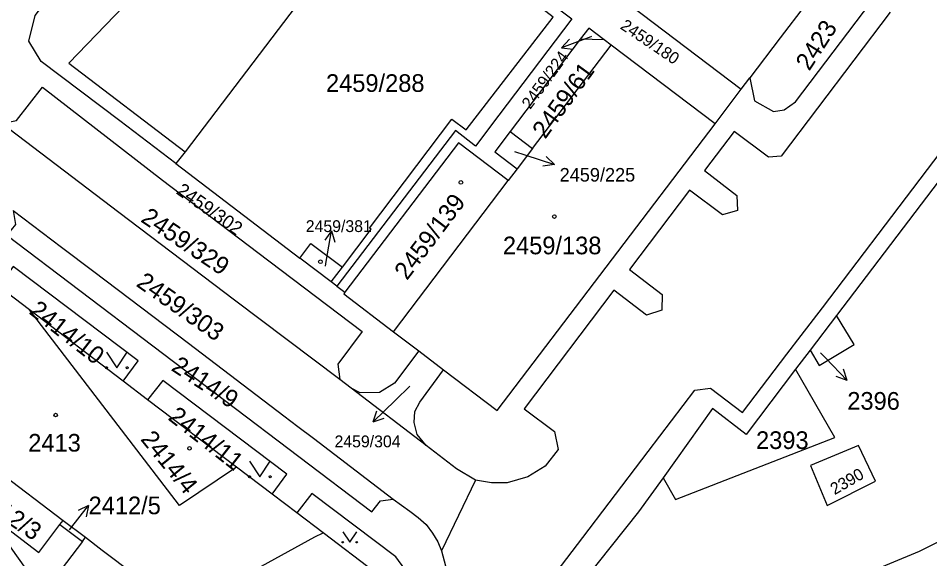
# Model space of a CAD drawing. Extents: x -606208 to -605570, y -1157873 to -1157573.
# Drawn here: x -605756.7 to -605669, y -1157686.5 to -1157634.5 of the extents above; entities that cross this region are included whole.
import ezdxf

# ---------------------------------------------------------------- set-up
doc = ezdxf.new("R2010")
doc.units = 0
doc.layers.add('Vrstva 62', color=7, linetype='Continuous')

msp = doc.modelspace()

# ---------------------------------------------------------------- linework, layer by layer
at = {"layer": 'Vrstva 62'}
for p, q in [((-605721.38, -1157621.96), (-605740.69, -1157647.37)), ((-605653.95, -1157631.43), (-605678, -1157663.1)), ((-605699.35, -1157632.1), (-605687.18, -1157641.34)), ((-605701.59, -1157636.26), (-605701.66, -1157636.28)), ((-605702.67, -1157636.52), (-605709.41, -1157645.4)), ((-605707.26, -1157647.03), (-605699.69, -1157637.08)), ((-605701.66, -1157636.28), (-605704.462, -1157637.355)), ((-605704.462, -1157637.355), (-605703.706, -1157636.529)), ((-605700.36, -1157636.57), (-605702.67, -1157636.52)), ((-605699.69, -1157637.08), (-605700.36, -1157636.57)), ((-605689.7, -1157644.66), (-605699.69, -1157637.08)), ((-605704.462, -1157637.355), (-605703.347, -1157637.464)), ((-605687.18, -1157641.34), (-605686.35, -1157640.24)), ((-605689.7, -1157644.66), (-605687.18, -1157641.34)), ((-605709.41, -1157645.4), (-605707.26, -1157647.03)), ((-605740.69, -1157647.37), (-605741.59, -1157648.49)), ((-605709, -1157647.32), (-605708.01, -1157647.65)), ((-605707.26, -1157647.03), (-605708.74, -1157648.98)), ((-605708.01, -1157647.65), (-605705.156, -1157648.577)), ((-605741.59, -1157648.49), (-605729.65, -1157657.58)), ((-605705.156, -1157648.577), (-605705.954, -1157647.792)), ((-605708.74, -1157648.98), (-605709.61, -1157650.13)), ((-605705.156, -1157648.577), (-605706.263, -1157648.744)), ((-605720.65, -1157664.67), (-605709.61, -1157650.13)), ((-605726.589, -1157654.975), (-605727.256, -1157655.874)), ((-605727.11, -1157657.93), (-605726.589, -1157654.975)), ((-605726.589, -1157654.975), (-605726.27, -1157656.048)), ((-605726.62, -1157659.88), (-605729.65, -1157657.58)), ((-605727.19, -1157658.35), (-605727.11, -1157657.93)), ((-605726.62, -1157659.88), (-605725.55, -1157658.46)), ((-605726.1, -1157660.28), (-605726.62, -1157659.88)), ((-605726.1, -1157660.28), (-605725.31, -1157660.88)), ((-605746.64, -1157669.44), (-605755.68, -1157662.57)), ((-605678, -1157663.1), (-605680.55, -1157666.45)), ((-605720.65, -1157664.67), (-605718.21, -1157666.52)), ((-605718.21, -1157666.52), (-605715.82, -1157668.34)), ((-605680.55, -1157666.45), (-605681.95, -1157668.29)), ((-605679.55, -1157666.71), (-605679.07, -1157667.2)), ((-605679.07, -1157667.2), (-605676.985, -1157669.359)), ((-605676.985, -1157669.359), (-605677.321, -1157668.29)), ((-605744.3, -1157671.22), (-605746.64, -1157669.44)), ((-605724.7, -1157670.12), (-605725.81, -1157669.27)), ((-605676.985, -1157669.359), (-605678.041, -1157668.986)), ((-605717.49, -1157675.62), (-605724.7, -1157670.12)), ((-605719.07, -1157669.91), (-605720.45, -1157671.26)), ((-605735.73, -1157677.72), (-605744.3, -1157671.22)), ((-605720.45, -1157671.26), (-605722.609, -1157673.345)), ((-605722.609, -1157673.345), (-605722.236, -1157672.289)), ((-605722.609, -1157673.345), (-605721.54, -1157673.009)), ((-605759.91, -1157677.16), (-605752.43, -1157682.83)), ((-605732.3, -1157680.32), (-605735.73, -1157677.72)), ((-605712.76, -1157678.96), (-605716.01, -1157685.76)), ((-605729.94, -1157682.1), (-605732.3, -1157680.32)), ((-605751.83, -1157683.75), (-605749.982, -1157681.385)), ((-605749.982, -1157681.385), (-605750.994, -1157681.866)), ((-605749.982, -1157681.385), (-605750.204, -1157682.483)), ((-605727.42, -1157684.02), (-605729.94, -1157682.1)), ((-605752.73, -1157683.23), (-605752.43, -1157682.83)), ((-605752.73, -1157683.23), (-605750.58, -1157684.86)), ((-605752.43, -1157682.83), (-605750.28, -1157684.46)), ((-605750.58, -1157684.86), (-605750.28, -1157684.46))]:
    msp.add_line(p, q, dxfattribs=at)
for points in [[(-605741.59, -1157648.49), (-605746.97, -1157644.39), (-605754.54, -1157638.66), (-605755.72, -1157636.71), (-605755.12, -1157634.23), (-605751.99, -1157630.1), (-605741.63, -1157616.42), (-605737.51, -1157610.98), (-605736.94, -1157610.24), (-605736.51, -1157609.73), (-605736.19, -1157609.53)], [(-605736.19, -1157609.53), (-605735.96, -1157609.49), (-605735.7, -1157609.4), (-605735.32, -1157609.39), (-605734.43, -1157609.77), (-605725.74, -1157616.38), (-605725.63, -1157617.79), (-605714.66, -1157626.08), (-605703.47, -1157634.55), (-605710.49, -1157643.82), (-605712.75, -1157646.8), (-605714.68, -1157645.32), (-605726.1, -1157660.28)], [(-605721.38, -1157621.96), (-605721.13, -1157621.62), (-605733.49, -1157612.23), (-605736.44, -1157620.16), (-605738.62, -1157619.25), (-605739.52, -1157620.49), (-605739.7, -1157620.36), (-605747.44, -1157630.54), (-605747.38, -1157630.72), (-605748.16, -1157631.81), (-605746.6, -1157633.34), (-605751.88, -1157638.81), (-605740.69, -1157647.37)], [(-605725.55, -1157658.46), (-605722.79, -1157654.79), (-605722.95, -1157654.71), (-605715.01, -1157644.22), (-605713.64, -1157645.23), (-605705.28, -1157634.41), (-605719.8, -1157623.18), (-605721.38, -1157621.96)], [(-605686.35, -1157640.24), (-605685.9, -1157642.45), (-605684.07, -1157643.47), (-605683.04, -1157643.33), (-605681.96, -1157642.56), (-605674.71, -1157633), (-605674.42, -1157631.08), (-605674.91, -1157629.9), (-605675.91, -1157628.98), (-605676.72, -1157628.38), (-605684.69, -1157622.37), (-605686.17, -1157624.31)], [(-605686.17, -1157624.31), (-605678.61, -1157630.05), (-605683.42, -1157636.39), (-605686.35, -1157640.24)], [(-605714.75, -1157700.25), (-605710.96, -1157695.68), (-605710.18, -1157694.65), (-605706.94, -1157690.4), (-605702.43, -1157684.48), (-605699.9, -1157681.15), (-605696.13, -1157676.2), (-605691.65, -1157670.31), (-605690.12, -1157670.1), (-605687.04, -1157672.45), (-605682.78, -1157666.84), (-605681.4, -1157665.03), (-605679.37, -1157662.36), (-605660.55, -1157637.61), (-605653.28, -1157627.99)], [(-605672.83, -1157633.91), (-605683.34, -1157647.76), (-605684.55, -1157647.87), (-605687.84, -1157645.41), (-605690.7, -1157649.16), (-605687.61, -1157651.55), (-605687.52, -1157653.02), (-605688.97, -1157653.43), (-605692.14, -1157651.06), (-605697.93, -1157658.7), (-605694.8, -1157661.08), (-605694.82, -1157662.59), (-605696.28, -1157663.07), (-605699.44, -1157660.68), (-605708.05, -1157672.09), (-605705.13, -1157674.27), (-605704.79, -1157676.02), (-605706.04, -1157677.6), (-605707.7, -1157678.63), (-605709.71, -1157679.22), (-605711.22, -1157679.22), (-605712.76, -1157678.96)], [(-605700.36, -1157636.57), (-605701.85, -1157635.44), (-605702.67, -1157636.52)], [(-605758.34, -1157644.62), (-605756.9, -1157644.34), (-605754.41, -1157641.15), (-605742.86, -1157650.08), (-605733.69, -1157657.06), (-605723.64, -1157664.65), (-605726.01, -1157667.78), (-605725.81, -1157669.27)], [(-605725.81, -1157669.27), (-605735.95, -1157661.62), (-605747.07, -1157653.21), (-605758.34, -1157644.62)], [(-605715.82, -1157668.34), (-605710.66, -1157672.26), (-605689.7, -1157644.66)], [(-605709.41, -1157645.4), (-605710.89, -1157647.35), (-605708.74, -1157648.98)], [(-605709.61, -1157650.13), (-605714.39, -1157646.5), (-605725.31, -1157660.88)], [(-605757.23, -1157653.01), (-605757.01, -1157654.35), (-605757.84, -1157655.37), (-605722.72, -1157682), (-605721.89, -1157680.95), (-605720.66, -1157680.78)], [(-605757.23, -1157653.01), (-605752.59, -1157656.53), (-605749.48, -1157658.89), (-605740.38, -1157665.78), (-605731.2, -1157672.77), (-605729.85, -1157673.79), (-605728.35, -1157674.93), (-605720.66, -1157680.78)], [(-605729.65, -1157657.58), (-605728.59, -1157656.17), (-605725.55, -1157658.46)], [(-605746.64, -1157669.44), (-605745.21, -1157667.49), (-605757.24, -1157658.39), (-605758.65, -1157660.32)], [(-605755.68, -1157662.57), (-605758.51, -1157660.43), (-605758.65, -1157660.32)], [(-605725.31, -1157660.88), (-605725.43, -1157661.04), (-605720.65, -1157664.67)], [(-605735.73, -1157677.72), (-605741.23, -1157681.4), (-605755.68, -1157662.57)], [(-605680.55, -1157666.45), (-605679.67, -1157667.91), (-605676.32, -1157665.89), (-605678, -1157663.1)], [(-605748.26, -1157666.639), (-605747.26, -1157668.14), (-605746.26, -1157666.639)], [(-605718.21, -1157666.52), (-605720.55, -1157669.64), (-605722, -1157670.51), (-605723.86, -1157670.55), (-605724.7, -1157670.12)], [(-605717.49, -1157675.62), (-605718.35, -1157674.56), (-605718.64, -1157673.42), (-605718.57, -1157672.35), (-605718.11, -1157671.46), (-605715.82, -1157668.34)], [(-605694.7, -1157678.73), (-605693.51, -1157680.83), (-605678.18, -1157674.85), (-605681.95, -1157668.29)], [(-605681.95, -1157668.29), (-605686.7, -1157674.55), (-605689.94, -1157672.07), (-605694.7, -1157678.73)], [(-605732.3, -1157680.32), (-605730.89, -1157678.38), (-605742.82, -1157669.36), (-605744.3, -1157671.22)], [(-605712.76, -1157678.96), (-605714.58, -1157677.86), (-605717.49, -1157675.62)], [(-605675.9, -1157675.63), (-605680.51, -1157677.56), (-605678.91, -1157681.4), (-605674.25, -1157679.05), (-605675.9, -1157675.63)], [(-605734.5, -1157677.129), (-605733.5, -1157678.63), (-605732.5, -1157677.129)], [(-605694.7, -1157678.73), (-605697.05, -1157682.01), (-605704.94, -1157691.92), (-605703.43, -1157692.73), (-605701.49, -1157693.29), (-605699.59, -1157693.2), (-605698.54, -1157697.8)], [(-605730.11, -1157697.93), (-605728.55, -1157699.16), (-605727.68, -1157699.35), (-605726.72, -1157699.08), (-605722.65, -1157695.57), (-605720.78, -1157693.46), (-605719.38, -1157691.41), (-605719.05, -1157689.39), (-605719.55, -1157687.53), (-605720.4, -1157686.35), (-605728.5, -1157680.23), (-605729.94, -1157682.1)], [(-605720.66, -1157680.78), (-605719.07, -1157681.94), (-605718.26, -1157682.55), (-605717.51, -1157683.23), (-605716.9, -1157684.05), (-605716.38, -1157684.91), (-605716.01, -1157685.76)], [(-605760, -1157681.95), (-605754.81, -1157689.23), (-605752.31, -1157687.79)], [(-605760, -1157681.95), (-605754.77, -1157685.92), (-605752.73, -1157683.23)], [(-605750.28, -1157684.46), (-605748.66, -1157685.69), (-605745.57, -1157688.03)], [(-605741.03, -1157691.47), (-605728.21, -1157684.4), (-605727.42, -1157684.02)], [(-605729.28, -1157696.78), (-605722.43, -1157687.81), (-605727.42, -1157684.02)], [(-605725.52, -1157683.924), (-605724.85, -1157684.93), (-605724.18, -1157683.924)], [(-605666.31, -1157683.93), (-605670.06, -1157685.83), (-605679.01, -1157689.56)], [(-605750.58, -1157684.86), (-605752.62, -1157687.55), (-605752.31, -1157687.79)], [(-605716.01, -1157685.76), (-605715.64, -1157687.2), (-605715.58, -1157688.54), (-605716.2, -1157690.79), (-605716.23, -1157690.9), (-605717.74, -1157692.92), (-605719.64, -1157695.24), (-605723.87, -1157699.35), (-605728.04, -1157702.31), (-605731.16, -1157703.8), (-605733.45, -1157704.9), (-605734.89, -1157705.42), (-605744.73, -1157708.97), (-605746.18, -1157708.32), (-605747.24, -1157705.75), (-605747.64, -1157704.79), (-605761.33, -1157709.71), (-605760.16, -1157713.04)]]:
    msp.add_lwpolyline(points, dxfattribs=at)
for centre, radius in [((-605714.147, -1157650.309), 0.175), ((-605705.157, -1157653.589), 0.175), ((-605727.667, -1157657.939), 0.175), ((-605748.26, -1157668.139), 0.1), ((-605746.26, -1157668.139), 0.1), ((-605753.147, -1157672.689), 0.175), ((-605740.267, -1157675.899), 0.175), ((-605734.5, -1157678.629), 0.1), ((-605732.5, -1157678.629), 0.1), ((-605725.52, -1157684.93), 0.067), ((-605724.18, -1157684.93), 0.067)]:
    msp.add_circle(centre, radius, dxfattribs=at)

# ---------------------------------------------------------------- texts
for s, height, rotation, p in [('2459/180', 1.139, 326, (-605698.899, -1157635.454)), ('2423', 1.7, 57, (-605680.63, -1157639.65)), ('2459/224', 1.139, 54, (-605707.472, -1157643.327)), ('2459/61', 1.7, 54, (-605706.04, -1157646.2)), ('2459/302', 1.288, 325, (-605741.63, -1157651.33)), ('2459/139', 1.7, 53, (-605719.336, -1157659.791)), ('2459/329', 1.7, 326, (-605745.05, -1157654.02)), ('2459/303', 1.7, 325, (-605745.49, -1157660.22)), ('2414/10', 1.7, 322, (-605755.8, -1157662.87)), ('2414/9', 1.7, 327, (-605742.12, -1157668.34)), ('2414/11', 1.7, 322, (-605742.42, -1157673.08)), ('2414/4', 1.7, 309, (-605745.042, -1157675.05)), ('2390', 1.139, 30, (-605678.19, -1157680.41)), ('2412/3', 1.7, 326, (-605761.03, -1157680.95))]:
    msp.add_text(s, height=height, rotation=rotation, dxfattribs=at).set_placement(p)
for s, height, p in [('2459/288', 1.7, (-605727.132, -1157641.59)), ('2459/225', 1.304, (-605704.651, -1157650.22)), ('2459/381', 1.139, (-605729.079, -1157655.08)), ('2459/138', 1.7, (-605710.11, -1157657.22)), ('2396', 1.7, (-605676.97, -1157672.18)), ('2413', 1.7, (-605755.786, -1157676.21)), ('2459/304', 1.139, (-605726.313, -1157675.8)), ('2393', 1.7, (-605685.75, -1157675.96)), ('2412/5', 1.7, (-605749.98, -1157682.24))]:
    msp.add_text(s, height=height, dxfattribs=at).set_placement(p)

doc.saveas('drawing.dxf')
